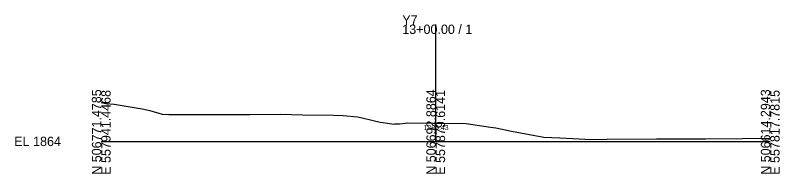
# Model space of a CAD drawing. Extents: x -26 to 557959, y -10 to 506992.
# Drawn here: x -25.7 to 202.8, y 2990.3 to 3037.8 of the extents above; entities that cross this region are included whole.
import ezdxf

# ---------------------------------------------------------------- set-up
doc = ezdxf.new("R2010")
doc.units = 0
for name, color, linetype in [('Default', 7, 'Continuous'), ('Exist Cross Section Cell', 7, 'Continuous'), ('Exist XS Center Line Elevation Label', 7, 'Continuous'), ('Exist XS Ground Line', 7, 'Continuous')]:
    doc.layers.add(name, color=color, linetype=linetype)

msp = doc.modelspace()

# ---------------------------------------------------------------- linework, layer by layer
at = {"layer": 'Exist Cross Section Cell'}
for p, q in [((100, 3000), (100, 3035)), ((0, 3000), (100, 3000)), ((100, 3000), (200, 3000))]:
    msp.add_line(p, q, dxfattribs=at)
at = {"layer": 'Exist XS Ground Line'}
for p, q in [((0, 3011.67), (1.38, 3011.37)), ((1.38, 3011.37), (3.84, 3011.19)), ((3.84, 3011.19), (12.21, 3009.71)), ((12.21, 3009.71), (14.5, 3009.27)), ((14.5, 3009.27), (18.18, 3008.17)), ((18.18, 3008.17), (20.26, 3008.04)), ((20.26, 3008.04), (30.38, 3008.09)), ((30.38, 3008.09), (35.35, 3008.03)), ((35.35, 3008.03), (44.36, 3008.09)), ((44.36, 3008.09), (53.5, 3008.12)), ((53.5, 3008.12), (60.29, 3007.99)), ((60.29, 3007.99), (69.42, 3007.83)), ((69.42, 3007.83), (72.31, 3007.79)), ((72.31, 3007.79), (76.57, 3007.35)), ((76.57, 3007.35), (78.01, 3007.08)), ((78.01, 3007.08), (81.27, 3006.27)), ((81.27, 3006.27), (83.4, 3005.81)), ((83.4, 3005.81), (84.25, 3005.63)), ((84.25, 3005.63), (87.48, 3005.18)), ((87.48, 3005.18), (87.78, 3005.28)), ((87.78, 3005.28), (89.18, 3005.28)), ((89.18, 3005.28), (90.87, 3005.44)), ((90.87, 3005.44), (91.44, 3005.57)), ((91.44, 3005.57), (99.26, 3005.44)), ((99.26, 3005.44), (100, 3005.43)), ((100, 3005.43), (100.44, 3005.43)), ((100.44, 3005.43), (101.7, 3005.42)), ((101.7, 3005.42), (109.14, 3005.36)), ((109.14, 3005.36), (116.37, 3004.27)), ((116.37, 3004.27), (117.99, 3004.07)), ((117.99, 3004.07), (122.63, 3003.11)), ((122.63, 3003.11), (132.33, 3001.31)), ((132.33, 3001.31), (137.06, 3001.04)), ((137.06, 3001.04), (142.92, 3000.77)), ((142.92, 3000.77), (144.54, 3000.7)), ((144.54, 3000.7), (147.33, 3000.54)), ((147.33, 3000.54), (151.25, 3000.7)), ((151.25, 3000.7), (165.96, 3000.75)), ((165.96, 3000.75), (172.95, 3000.8)), ((172.95, 3000.8), (179.18, 3000.75)), ((179.18, 3000.75), (180.75, 3000.73)), ((180.75, 3000.73), (181.93, 3000.84)), ((181.93, 3000.84), (189.87, 3000.76)), ((189.87, 3000.76), (191.63, 3000.9)), ((191.63, 3000.9), (200, 3000.95))]:
    msp.add_line(p, q, dxfattribs=at)

# ---------------------------------------------------------------- texts
at = {"layer": 'Default'}
msp.add_text('-', height=0.0001, dxfattribs=at).set_placement((0, 3000))
at = {"layer": 'Exist Cross Section Cell'}
for s, p in [('Y7', (90, 3035)), ('13+00.00 / 1', (90, 3032.2)), ('EL 1864', (-26, 2998.6))]:
    msp.add_text(s, height=2.8, dxfattribs=at).set_placement(p)
for s, p in [('N 506771.4785', (0, 2990)), ('E 557941.4468', (2.8, 2990)), ('N 506692.8864', (100, 2990)), ('E 557879.6141', (102.8, 2990)), ('N 506614.2943', (200, 2990)), ('E 557817.7815', (202.8, 2990))]:
    msp.add_text(s, height=2.8, rotation=90, dxfattribs=at).set_placement(p)
at = {"layer": 'Exist XS Center Line Elevation Label'}
msp.add_text('1869.43', height=1.5, dxfattribs=at).set_placement((96.36, 3003.39))

doc.saveas('drawing.dxf')
